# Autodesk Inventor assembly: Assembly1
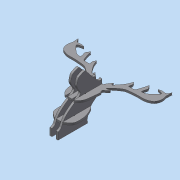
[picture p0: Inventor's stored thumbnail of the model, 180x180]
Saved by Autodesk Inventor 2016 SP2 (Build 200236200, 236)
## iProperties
Created: 2017-07
Part Number: Assembly1
Document SubType Name: Assembly
Designer: Mohamed A.
Author: Mohamed A.
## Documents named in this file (4)
- C:\Users\Mohamed\Documents\inventor\cam\Assembly1.iam
- C:\Users\Mohamed\Documents\inventor\cam\Part1.ipt
- C:\Users\Mohamed\Documents\inventor\cam\Part2.ipt
- C:\Users\Mohamed\Documents\inventor\cam\Part3.ipt
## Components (4 placed, 3 different names)
1. Part1:1 — Mate:1, Mate:2, Mate:3, Mate:7, Mate:8, Mate:9
2. Part2:1 — Mate:4, Mate:5, Mate:6
3. Part3:1 — Mate:1, Mate:2, Mate:3, Mate:4, Mate:5, Mate:6
4. Part3:2 — Mate:7, Mate:8, Mate:9
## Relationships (9: Mate 9)
- Mate:1: Part1:1 ↔ Part3:1
- Mate:2: Part1:1 ↔ Part3:1
- Mate:3: Part1:1 ↔ Part3:1
- Mate:4: Part2:1 ↔ Part3:1
- Mate:5: Part2:1 ↔ Part3:1
- Mate:6: Part2:1 ↔ Part3:1
- Mate:7: Part1:1 ↔ Part3:2
- Mate:8: Part1:1 ↔ Part3:2
- Mate:9: Part1:1 ↔ Part3:2
